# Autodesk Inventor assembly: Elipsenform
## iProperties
Created: 2005-01
Part Number: Elipsenform
Document SubType Name: Assembly
Designer: KK
Manufacturer: Standard
Standards Organization: Custom
Description: GLASSCHNITT SIMI Ø150
AIMD_DESCRIPTION: KOMPLETT
Author: KK
Title: GLASSCHNITT SIMI Ø150
